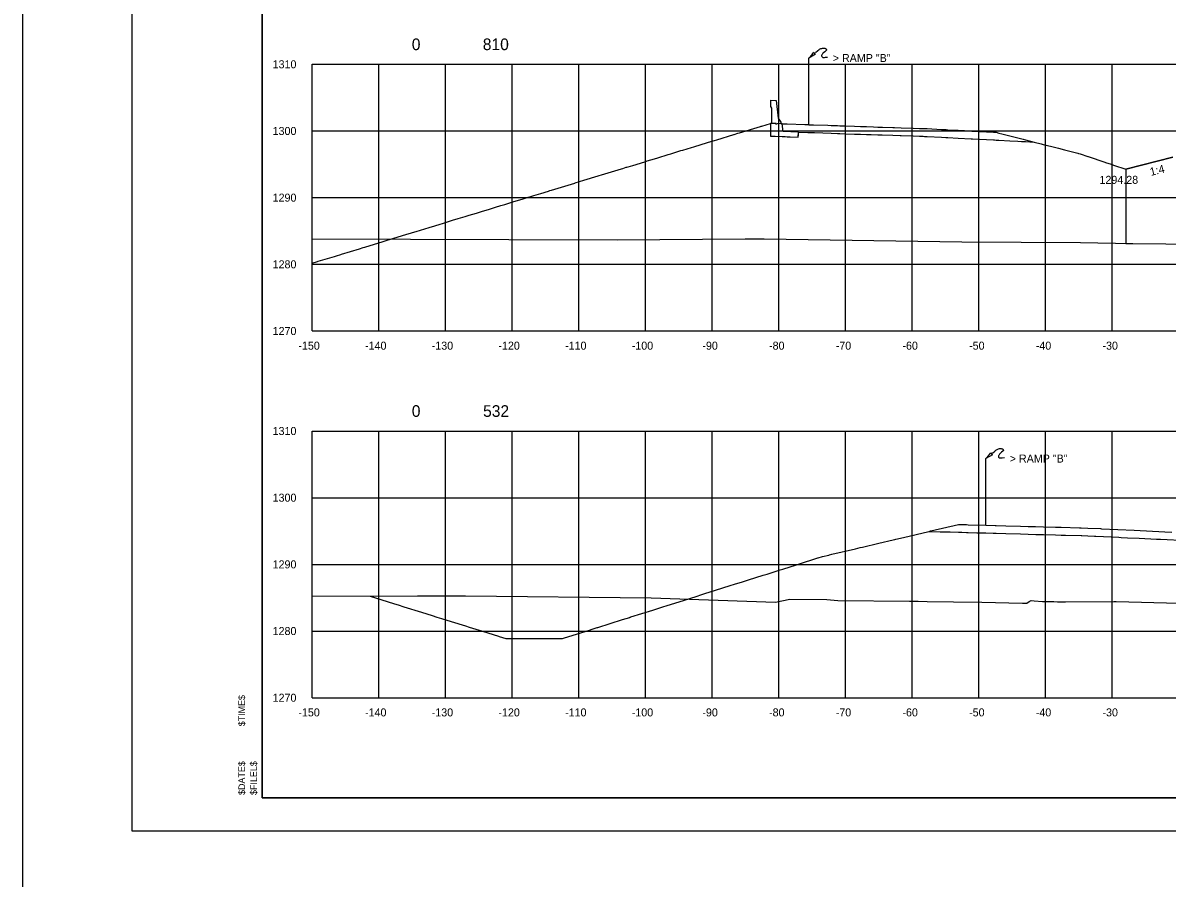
# Model space of a CAD drawing. Extents: x 2148105 to 2149976, y 144169 to 149705.
# Drawn here: x 2148219.9 to 2148391.5, y 144909.9 to 145038.1 of the extents above; entities that cross this region are included whole.
import ezdxf

# ---------------------------------------------------------------- set-up
doc = ezdxf.new("R2010")
doc.units = 0
for name, color, linetype in [('EX_Align', 7, 'Continuous'), ('INR_Tracking', 7, 'Continuous'), ('PH1a-2-RampC', 7, 'Continuous'), ('PH1a-PR-DividingStrip', 7, 'Continuous'), ('PH1a-PR-Drives', 7, 'Continuous'), ('PH1a-PR-ServRd', 7, 'Continuous'), ('PR-Dividing Strip', 7, 'Continuous'), ('PR_Align_PC', 7, 'Continuous'), ('PR_Align_PI', 7, 'Continuous'), ('PR_Align_Ramp_E', 7, 'Continuous'), ('PR_Align_Ramp_J', 7, 'Continuous'), ('PR_Storm_Conc_Box_PH1B', 7, 'Continuous'), ('PR_Storm_Conc_Pipe_PH1B', 7, 'Continuous'), ('PR_Storm_Inlet_CICI_PH1A', 7, 'Continuous'), ('PR_Storm_Inlet_CICI_PH1B', 7, 'Continuous'), ('PR_Storm_MH_PH1B', 7, 'Continuous'), ('PR_Storm_Standard_Median_Drain_PH1B', 7, 'Continuous'), ('TopCut', 7, 'Continuous')]:
    doc.layers.add(name, color=color, linetype=linetype)

msp = doc.modelspace()

# ---------------------------------------------------------------- linework, layer by layer
at = {"layer": 'EX_Align'}
for points in [[(2148263.32, 145002.08), (2148264.14, 145002.33), (2148264.25, 145002.37), (2148266.66, 145003.1), (2148266.99, 145003.2), (2148267.65, 145003.4), (2148267.75, 145003.43), (2148270.42, 145004.25), (2148270.97, 145004.41), (2148271.2, 145004.48), (2148271.25, 145004.5), (2148273.99, 145005.34), (2148274.74, 145005.57), (2148274.89, 145005.61), (2148274.94, 145005.63), (2148277.38, 145006.37), (2148278.24, 145006.63), (2148278.72, 145006.78), (2148278.91, 145006.84), (2148280.87, 145007.44), (2148281.73, 145007.7), (2148282.51, 145007.94), (2148282.89, 145008.05), (2148284.4, 145008.51), (2148285.23, 145008.77), (2148286.25, 145009.08), (2148286.86, 145009.26), (2148287.98, 145009.6), (2148288.73, 145009.83), (2148289.94, 145010.2), (2148290.83, 145010.47), (2148291.6, 145010.71), (2148292.22, 145010.9), (2148293.58, 145011.31), (2148294.8, 145011.69), (2148295.27, 145011.83), (2148295.72, 145011.97), (2148296.13, 145012.09), (2148296.56, 145012.22), (2148297.61, 145012.54), (2148298.78, 145012.9), (2148298.98, 145012.96), (2148299.22, 145013.03), (2148300.72, 145013.49), (2148302.71, 145014.1), (2148302.73, 145014.1), (2148302.75, 145014.11), (2148304.08, 145014.52), (2148306.21, 145015.17), (2148306.39, 145015.22), (2148306.72, 145015.32), (2148307.73, 145015.63), (2148309.71, 145016.23), (2148309.93, 145016.3), (2148310.44, 145016.46), (2148310.52, 145016.48), (2148310.7, 145016.54), (2148311.41, 145016.75), (2148313.2, 145017.3), (2148313.58, 145017.41), (2148314.67, 145017.75), (2148315.15, 145017.89), (2148316.7, 145018.37), (2148317.1, 145018.49), (2148318.64, 145018.96), (2148318.93, 145019.04), (2148320.2, 145019.43), (2148320.58, 145019.55), (2148322.62, 145020.17), (2148322.76, 145020.21), (2148323.69, 145020.5), (2148324.02, 145020.6), (2148326.59, 145021.38), (2148326.64, 145021.39), (2148327.19, 145021.56), (2148327.41, 145021.63), (2148330.56, 145022.59), (2148330.57, 145022.59), (2148330.68, 145022.63), (2148330.75, 145022.65), (2148332.06, 145023.05), (2148332.06, 145022.34), (2148332.07, 145021.88), (2148332.07, 145021.43), (2148332.08, 145021.13), (2148332.77, 145021.11), (2148333.8, 145021.07), (2148333.96, 145021.06), (2148334.18, 145021.06), (2148334.25, 145021.06), (2148334.54, 145021.05), (2148336.23, 145020.99), (2148336.24, 145021.33), (2148336.24, 145021.74), (2148337.68, 145021.69), (2148337.72, 145021.69), (2148337.8, 145021.69), (2148338.47, 145021.66), (2148338.51, 145021.66), (2148338.66, 145021.66), (2148341.17, 145021.57), (2148342.12, 145021.54), (2148342.48, 145021.53), (2148343.24, 145021.5), (2148344.67, 145021.45), (2148345.55, 145021.42), (2148346.46, 145021.39), (2148347.15, 145021.37), (2148348.17, 145021.34), (2148348.83, 145021.31), (2148350.43, 145021.26), (2148351.51, 145021.22), (2148351.66, 145021.22), (2148353.45, 145021.16), (2148354.4, 145021.13), (2148354.94, 145021.11), (2148355.16, 145021.1), (2148355.39, 145021.09), (2148355.54, 145021.09), (2148357.71, 145020.97), (2148358.38, 145020.94), (2148358.45, 145020.93), (2148358.66, 145020.92), (2148360.23, 145020.84), (2148362.15, 145020.74), (2148362.28, 145020.73), (2148362.35, 145020.73), (2148365.53, 145020.56), (2148365.65, 145020.56), (2148365.89, 145020.54), (2148366.32, 145020.52), (2148367.95, 145020.43), (2148369.14, 145020.37), (2148369.69, 145020.34), (2148370.3, 145020.31), (2148371.62, 145020.24), (2148372.64, 145019.98), (2148372.96, 145019.9), (2148374.27, 145019.56), (2148375.26, 145019.31), (2148376.14, 145019.08), (2148378.13, 145018.57), (2148378.24, 145018.54), (2148378.5, 145018.48), (2148379.63, 145018.1), (2148379.71, 145018.07), (2148382.21, 145017.23), (2148382.3, 145017.2), (2148383.13, 145016.92), (2148383.49, 145016.8), (2148385.33, 145016.18)], [(2148272.02, 144952.15), (2148275.52, 144951.05), (2148276.37, 144950.79), (2148276.92, 144950.61), (2148277.1, 144950.56), (2148279.72, 144949.73), (2148281.33, 144949.23), (2148282.04, 144949.01), (2148282.74, 144948.79), (2148284.17, 144948.34), (2148286.3, 144947.67), (2148286.86, 144947.5), (2148288.38, 144947.02), (2148288.87, 144946.87), (2148291.26, 144946.12), (2148291.39, 144946.07), (2148292.38, 144945.77), (2148293.37, 144945.77), (2148294.03, 144945.77), (2148294.91, 144945.77), (2148296.23, 144945.77), (2148296.4, 144945.77), (2148296.61, 144945.77), (2148298.3, 144945.77), (2148299.67, 144945.77), (2148299.98, 144945.77), (2148300.85, 144945.78), (2148301.18, 144945.88), (2148301.19, 144945.88), (2148304.9, 144947.05), (2148305.31, 144947.18), (2148306.05, 144947.42), (2148306.16, 144947.45), (2148309.88, 144948.62), (2148310.95, 144948.96), (2148310.96, 144948.97), (2148311.08, 144949), (2148311.08, 144949), (2148311.12, 144949.02), (2148314.41, 144950.05), (2148316.09, 144950.58), (2148316.4, 144950.68), (2148316.59, 144950.74), (2148319.02, 144951.51), (2148321.05, 144952.15), (2148321.62, 144952.33), (2148322.24, 144952.52), (2148323.83, 144953.03), (2148326.02, 144953.72), (2148326.66, 144953.92), (2148327.88, 144954.31), (2148328.78, 144954.59), (2148330.98, 144955.29), (2148331.54, 144955.46), (2148333.52, 144956.09), (2148333.9, 144956.21), (2148335.95, 144956.85), (2148336.25, 144956.95), (2148339.16, 144957.87), (2148339.19, 144957.88), (2148339.84, 144958.08), (2148340.81, 144958.31), (2148340.91, 144958.33), (2148341.26, 144958.42), (2148344.8, 144959.25), (2148345.5, 144959.42), (2148345.88, 144959.51), (2148348.29, 144960.08), (2148350.45, 144960.59), (2148350.72, 144960.65), (2148350.84, 144960.68), (2148352.03, 144960.96), (2148355.81, 144961.85), (2148355.84, 144961.86), (2148356.09, 144961.85), (2148357.5, 144961.81), (2148358.21, 144961.79), (2148358.99, 144961.77), (2148360.25, 144961.74), (2148360.5, 144961.73), (2148360.77, 144961.72), (2148361.45, 144961.7), (2148361.73, 144961.7), (2148363.02, 144961.66), (2148364.34, 144961.62), (2148365.45, 144961.59), (2148365.74, 144961.58), (2148365.91, 144961.58), (2148367.37, 144961.54), (2148369.57, 144961.48), (2148370.7, 144961.44), (2148371.84, 144961.41), (2148373.02, 144961.38), (2148374.83, 144961.33), (2148375.67, 144961.3), (2148376.32, 144961.29), (2148378.66, 144961.22), (2148378.77, 144961.22), (2148379.65, 144961.19), (2148380.63, 144961.14), (2148380.87, 144961.13), (2148384.3, 144960.97), (2148384.64, 144960.95), (2148385.6, 144960.91), (2148387.36, 144960.82), (2148389.94, 144960.7), (2148390.29, 144960.68), (2148390.56, 144960.67), (2148394.48, 144960.48)]]:
    msp.add_lwpolyline(points, dxfattribs=at)
at = {"layer": 'INR_Tracking'}
msp.add_lwpolyline([(2148385.33, 145016.18), (2148392.42, 145017.96)], dxfattribs=at)
at = {"layer": 'PH1a-PR-ServRd'}
msp.add_lwpolyline([(2148570.82, 144921.91), (2148255.82, 144921.91), (2148255.82, 145131.91), (2148570.82, 145131.91)], close=True, dxfattribs=at)
at = {"layer": 'PR-Dividing Strip'}
for p, q in [((2148337.8, 145022.85), (2148337.8, 145032.85)), ((2148364.34, 144962.79), (2148364.34, 144972.79))]:
    msp.add_line(p, q, dxfattribs=at)
for points in [[(2148337.8, 145032.85), (2148338.32, 145033.4), (2148338.58, 145033.71), (2148338.66, 145033.54), (2148338.8, 145033.43), (2148337.8, 145032.85)], [(2148338.81, 145033.66), (2148339.16, 145033.96), (2148339.33, 145034.08), (2148339.42, 145034.16), (2148339.52, 145034.21), (2148339.62, 145034.26), (2148339.74, 145034.3), (2148339.87, 145034.33), (2148339.96, 145034.34), (2148340.05, 145034.34), (2148340.13, 145034.33), (2148340.2, 145034.32), (2148340.25, 145034.3), (2148340.31, 145034.28), (2148340.35, 145034.25), (2148340.39, 145034.22), (2148340.42, 145034.18), (2148340.45, 145034.12), (2148340.45, 145034.07), (2148340.44, 145034.03), (2148340.39, 145033.96), (2148340.2, 145033.8), (2148340.01, 145033.63), (2148339.93, 145033.56), (2148339.87, 145033.48), (2148339.81, 145033.39), (2148339.77, 145033.33), (2148339.73, 145033.24), (2148339.73, 145033.16), (2148339.75, 145033.08), (2148339.79, 145033.01), (2148339.84, 145032.97), (2148339.9, 145032.95), (2148340.01, 145032.93), (2148340.14, 145032.94), (2148340.3, 145032.96), (2148340.63, 145032.99)], [(2148364.34, 144972.79), (2148364.85, 144973.34), (2148365.11, 144973.65), (2148365.2, 144973.48), (2148365.34, 144973.36), (2148364.34, 144972.79)], [(2148365.35, 144973.6), (2148365.7, 144973.89), (2148365.86, 144974.02), (2148365.96, 144974.1), (2148366.06, 144974.15), (2148366.16, 144974.2), (2148366.27, 144974.24), (2148366.41, 144974.27), (2148366.5, 144974.27), (2148366.58, 144974.27), (2148366.67, 144974.27), (2148366.74, 144974.25), (2148366.79, 144974.24), (2148366.85, 144974.22), (2148366.89, 144974.19), (2148366.93, 144974.16), (2148366.96, 144974.12), (2148366.99, 144974.06), (2148366.99, 144974), (2148366.98, 144973.96), (2148366.92, 144973.89), (2148366.73, 144973.73), (2148366.55, 144973.57), (2148366.47, 144973.49), (2148366.41, 144973.42), (2148366.35, 144973.32), (2148366.31, 144973.26), (2148366.27, 144973.17), (2148366.26, 144973.1), (2148366.28, 144973.01), (2148366.33, 144972.94), (2148366.38, 144972.91), (2148366.43, 144972.89), (2148366.54, 144972.87), (2148366.68, 144972.88), (2148366.83, 144972.89), (2148367.17, 144972.93)]]:
    msp.add_lwpolyline(points, dxfattribs=at)
at = {"layer": 'PR_Align_PI'}
for points in [[(2148333.8, 145022.99), (2148334, 145022.98), (2148334.18, 145022.97), (2148334.48, 145022.96), (2148334.54, 145022.96), (2148337.22, 145022.87), (2148337.68, 145022.86), (2148337.7, 145022.86), (2148337.8, 145022.85), (2148338.48, 145022.83), (2148338.51, 145022.83), (2148340.68, 145022.76), (2148341.17, 145022.74), (2148342.12, 145022.71), (2148342.48, 145022.69), (2148343.24, 145022.67), (2148344.67, 145022.62), (2148345.57, 145022.59), (2148346.46, 145022.56), (2148347.52, 145022.52), (2148348.17, 145022.5), (2148348.84, 145022.48), (2148350.43, 145022.43), (2148350.65, 145022.42), (2148351.66, 145022.39), (2148353.45, 145022.32), (2148354.4, 145022.29), (2148354.94, 145022.28), (2148355.16, 145022.27), (2148355.54, 145022.26), (2148357.71, 145022.14), (2148358.38, 145022.11), (2148358.45, 145022.1), (2148358.66, 145022.09), (2148360.23, 145022.01), (2148362.15, 145021.91), (2148362.28, 145021.9), (2148362.35, 145021.9), (2148365.53, 145021.73), (2148365.65, 145021.72), (2148365.89, 145021.71), (2148366.32, 145021.6), (2148366.74, 145021.49), (2148369.14, 145020.88), (2148369.96, 145020.67), (2148370.29, 145020.58), (2148371.62, 145020.24)], [(2148355.84, 144961.86), (2148356.07, 144961.92), (2148356.09, 144961.92), (2148360.25, 144962.9), (2148360.77, 144962.89), (2148361.45, 144962.87), (2148361.73, 144962.86), (2148364.34, 144962.79), (2148365.74, 144962.75), (2148365.91, 144962.74), (2148367.37, 144962.7), (2148369.57, 144962.64), (2148370.7, 144962.61), (2148371.83, 144962.58), (2148373.01, 144962.55), (2148374.83, 144962.49), (2148375.67, 144962.47), (2148378.42, 144962.39), (2148378.66, 144962.39), (2148379.65, 144962.36), (2148381.57, 144962.27), (2148381.71, 144962.26), (2148386.59, 144962.03), (2148391.2, 144961.81), (2148392.26, 144961.76)]]:
    msp.add_lwpolyline(points, dxfattribs=at)
at = {"layer": 'PR_Align_Ramp_E'}
msp.add_lwpolyline([(2148219.95, 145145.16), (2148579.95, 145145.16), (2148579.95, 144905.16), (2148219.95, 144905.16)], close=True, dxfattribs=at)
at = {"layer": 'PR_Align_Ramp_J'}
msp.add_lwpolyline([(2148236.32, 145136.91), (2148576.32, 145136.91), (2148576.32, 144916.91), (2148236.32, 144916.91)], close=True, dxfattribs=at)
at = {"layer": 'PR_Storm_Conc_Box_PH1B'}
for p, q in [((2148263.32, 145031.91), (2148563.32, 145031.91)), ((2148263.32, 144991.91), (2148263.32, 145031.91)), ((2148273.32, 144991.91), (2148273.32, 145031.91)), ((2148283.32, 144991.91), (2148283.32, 145031.91)), ((2148293.32, 144991.91), (2148293.32, 145031.91)), ((2148303.32, 144991.91), (2148303.32, 145031.91)), ((2148313.32, 144991.91), (2148313.32, 145031.91)), ((2148323.32, 144991.91), (2148323.32, 145031.91)), ((2148333.32, 144991.91), (2148333.32, 145031.91)), ((2148343.32, 144991.91), (2148343.32, 145031.91)), ((2148353.32, 144991.91), (2148353.32, 145031.91)), ((2148363.32, 144991.91), (2148363.32, 145031.91)), ((2148373.32, 144991.91), (2148373.32, 145031.91)), ((2148383.32, 144991.91), (2148383.32, 145031.91)), ((2148263.32, 145021.91), (2148563.32, 145021.91)), ((2148263.32, 145011.91), (2148563.32, 145011.91)), ((2148263.32, 145001.91), (2148563.32, 145001.91)), ((2148263.32, 144991.91), (2148563.32, 144991.91)), ((2148263.32, 144976.91), (2148563.32, 144976.91)), ((2148263.32, 144936.91), (2148263.32, 144976.91)), ((2148273.32, 144936.91), (2148273.32, 144976.91)), ((2148283.32, 144936.91), (2148283.32, 144976.91)), ((2148293.32, 144936.91), (2148293.32, 144976.91)), ((2148303.32, 144936.91), (2148303.32, 144976.91)), ((2148313.32, 144936.91), (2148313.32, 144976.91)), ((2148323.32, 144936.91), (2148323.32, 144976.91)), ((2148333.32, 144936.91), (2148333.32, 144976.91)), ((2148343.32, 144936.91), (2148343.32, 144976.91)), ((2148353.32, 144936.91), (2148353.32, 144976.91)), ((2148363.32, 144936.91), (2148363.32, 144976.91)), ((2148373.32, 144936.91), (2148373.32, 144976.91)), ((2148383.32, 144936.91), (2148383.32, 144976.91)), ((2148263.32, 144966.91), (2148563.32, 144966.91)), ((2148263.32, 144956.91), (2148563.32, 144956.91)), ((2148263.32, 144946.91), (2148563.32, 144946.91)), ((2148263.32, 144936.91), (2148563.32, 144936.91))]:
    msp.add_line(p, q, dxfattribs=at)
at = {"layer": 'PR_Storm_Conc_Pipe_PH1B'}
msp.add_lwpolyline([(2148255.82, 144921.91), (2148570.82, 144921.91), (2148570.82, 145131.91), (2148255.82, 145131.91)], close=True, dxfattribs=at)
msp.add_lwpolyline([(2148255.82, 144921.91), (2148570.82, 144921.91), (2148570.82, 145131.91), (2148255.82, 145131.91)], close=True, dxfattribs=at)
at = {"layer": 'PR_Storm_Inlet_CICI_PH1A'}
for points in [[(2148332.25, 145023.04), (2148332.26, 145025.32), (2148332.13, 145025.59), (2148332.13, 145026.51), (2148332.91, 145026.5), (2148333.21, 145023.83), (2148333.62, 145023.24), (2148333.63, 145022.99), (2148333.02, 145023.01), (2148333.02, 145022.93), (2148332.84, 145022.94), (2148332.84, 145023.02)], [(2148332.25, 145023.04), (2148332.26, 145025.32), (2148332.13, 145025.59), (2148332.13, 145026.51), (2148332.91, 145026.5), (2148333.21, 145023.83), (2148333.62, 145023.24), (2148333.63, 145022.99), (2148333.02, 145023.01), (2148333.02, 145022.93), (2148332.84, 145022.94), (2148332.84, 145023.02)], [(2148332.08, 145021.13), (2148333.8, 145021.07), (2148336.23, 145020.99), (2148336.24, 145021.74), (2148333.98, 145021.81), (2148333.8, 145022.99), (2148333.63, 145022.99), (2148333.02, 145023.01), (2148333.02, 145022.93), (2148332.84, 145022.94), (2148332.84, 145023.02), (2148332.25, 145023.04), (2148332.06, 145023.05), (2148332.07, 145021.88)], [(2148332.08, 145021.13), (2148333.8, 145021.07), (2148336.23, 145020.99), (2148336.24, 145021.74), (2148333.98, 145021.81), (2148333.8, 145022.99), (2148333.63, 145022.99), (2148333.02, 145023.01), (2148333.02, 145022.93), (2148332.84, 145022.94), (2148332.84, 145023.02), (2148332.25, 145023.04), (2148332.06, 145023.05), (2148332.07, 145021.88)]]:
    msp.add_lwpolyline(points, close=True, dxfattribs=at)
at = {"layer": 'PR_Storm_Inlet_CICI_PH1B'}
for points in [[(2148263.32, 145005.75), (2148292.83, 145005.64), (2148309.08, 145005.56), (2148328.28, 145005.73), (2148331.13, 145005.73), (2148360.77, 145005.28), (2148378.54, 145005.16), (2148386.4, 145005.01), (2148391.37, 145004.96), (2148395.46, 145004.94)], [(2148263.32, 144952.12), (2148279.15, 144952.17), (2148283.14, 144952.2), (2148284.79, 144952.19), (2148286.32, 144952.19), (2148314.19, 144951.9), (2148332.8, 144951.26), (2148334.94, 144951.69), (2148340.53, 144951.64), (2148342.17, 144951.47), (2148352.91, 144951.38), (2148354.19, 144951.39), (2148355.54, 144951.35), (2148359.52, 144951.29), (2148363.74, 144951.26), (2148369.87, 144951.07), (2148370.09, 144951.09), (2148370.51, 144951.1), (2148370.86, 144951.35), (2148371.16, 144951.5), (2148371.63, 144951.46), (2148372.85, 144951.36), (2148373.54, 144951.36), (2148374, 144951.34), (2148374.56, 144951.32), (2148375.09, 144951.31), (2148376.29, 144951.27), (2148383.57, 144951.36), (2148383.92, 144951.36), (2148393.36, 144951.11)]]:
    msp.add_lwpolyline(points, dxfattribs=at)
at = {"layer": 'PR_Storm_Standard_Median_Drain_PH1B'}
for p, q in [((2148263.32, 144991.91), (2148263.32, 145031.91)), ((2148263.32, 144991.91), (2148563.32, 144991.91)), ((2148263.32, 144936.91), (2148263.32, 144976.91)), ((2148263.32, 144936.91), (2148563.32, 144936.91))]:
    msp.add_line(p, q, dxfattribs=at)
at = {"layer": 'TopCut'}
msp.add_lwpolyline([(2148392.42, 145017.96), (2148385.33, 145016.18), (2148385.33, 145005.03), (2148386.4, 145005.01), (2148391.37, 145004.96), (2148395.46, 145004.94)], dxfattribs=at)

# ---------------------------------------------------------------- texts
at = {"layer": 'PH1a-2-RampC'}
msp.add_text('1294.28', height=1.2, dxfattribs=at).set_placement((2148381.4, 145013.98))
at = {"layer": 'PH1a-PR-DividingStrip'}
msp.add_text('1:4', height=1.2, rotation=14.0318, dxfattribs=at).set_placement((2148389.11, 145015.16))
at = {"layer": 'PH1a-PR-Drives'}
for s, p in [('$TIME$', (2148253.27, 144932.63)), ('$DATE$', (2148253.27, 144922.33)), ('$FILEL$', (2148255.05, 144922.33))]:
    msp.add_text(s, height=1, rotation=90, dxfattribs=at).set_placement(p)
at = {"layer": 'PR-Dividing Strip'}
for p in [(2148341.4, 145032.25), (2148367.94, 144972.18)]:
    msp.add_text('> RAMP "B"', height=1.2, rotation=360, dxfattribs=at).set_placement(p)
at = {"layer": 'PR_Align_PC'}
for s, p in [('0', (2148278.27, 145034.03)), ('810', (2148288.92, 145034.03)), ('0', (2148278.27, 144979.03)), ('532', (2148288.96, 144979.03))]:
    msp.add_text(s, height=1.75, dxfattribs=at).set_placement(p)
at = {"layer": 'PR_Storm_MH_PH1B'}
for s, p in [('1310', (2148257.4, 145031.31)), ('1300', (2148257.4, 145021.31)), ('1290', (2148257.4, 145011.31)), ('1280', (2148257.4, 145001.31)), ('1270', (2148257.4, 144991.31)), ('-150', (2148261.26, 144989.11)), ('-140', (2148271.26, 144989.11)), ('-130', (2148281.26, 144989.11)), ('-120', (2148291.26, 144989.11)), ('-110', (2148301.26, 144989.11)), ('-100', (2148311.26, 144989.11)), ('-90', (2148321.85, 144989.11)), ('-80', (2148331.85, 144989.11)), ('-70', (2148341.85, 144989.11)), ('-60', (2148351.85, 144989.11)), ('-50', (2148361.85, 144989.11)), ('-40', (2148371.85, 144989.11)), ('-30', (2148381.85, 144989.11)), ('1310', (2148257.4, 144976.31)), ('1300', (2148257.4, 144966.31)), ('1290', (2148257.4, 144956.31)), ('1280', (2148257.4, 144946.31)), ('1270', (2148257.4, 144936.31)), ('-150', (2148261.26, 144934.11)), ('-140', (2148271.26, 144934.11)), ('-130', (2148281.26, 144934.11)), ('-120', (2148291.26, 144934.11)), ('-110', (2148301.26, 144934.11)), ('-100', (2148311.26, 144934.11)), ('-90', (2148321.85, 144934.11)), ('-80', (2148331.85, 144934.11)), ('-70', (2148341.85, 144934.11)), ('-60', (2148351.85, 144934.11)), ('-50', (2148361.85, 144934.11)), ('-40', (2148371.85, 144934.11)), ('-30', (2148381.85, 144934.11))]:
    msp.add_text(s, height=1.2, dxfattribs=at).set_placement(p)

doc.saveas('drawing.dxf')
